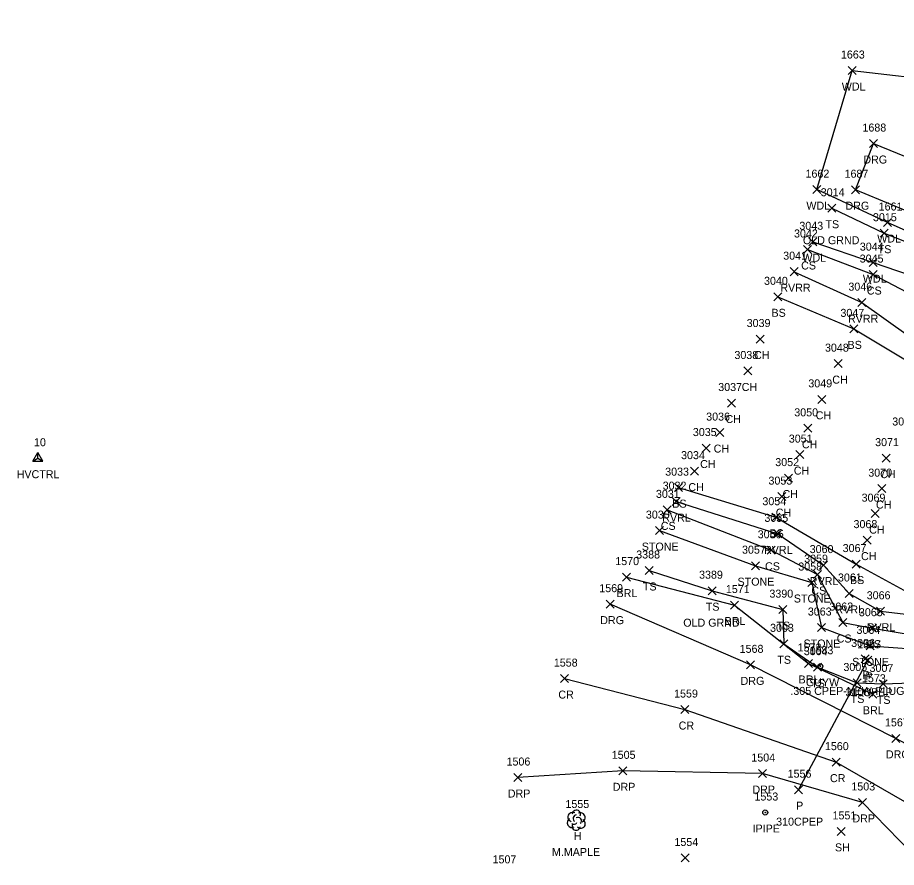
# Model space of a CAD drawing. Extents: x 462930 to 463548, y 29607 to 30453.
# Drawn here: x 463253.6 to 463320.6, y 30111.1 to 30175.8 of the extents above; entities that cross this region are included whole.
import ezdxf

# ---------------------------------------------------------------- set-up
doc = ezdxf.new("R2010")
doc.units = 0
for name, color, linetype in [('C_A', 7, 'Continuous'), ('C_I', 7, 'Continuous'), ('CPSM', 7, 'Continuous'), ('D_A', 7, 'Continuous'), ('D_C', 7, 'Continuous'), ('D_I', 7, 'Continuous'), ('D_TIC', 7, 'Continuous'), ('DCP', 7, 'Continuous'), ('L_A', 7, 'Continuous'), ('L_C', 7, 'Continuous'), ('L_I', 7, 'Continuous'), ('L_TIC', 7, 'Continuous'), ('LABL', 7, 'Continuous'), ('LASF', 7, 'Continuous'), ('LAWA', 7, 'Continuous'), ('LAWE', 7, 'Continuous'), ('LELB', 7, 'Continuous'), ('LTD', 7, 'Continuous'), ('M_A', 7, 'Continuous'), ('M_I', 7, 'Continuous'), ('MPIP', 7, 'Continuous'), ('P_A', 7, 'Continuous'), ('P_I', 7, 'Continuous'), ('P_TIC', 7, 'Continuous'), ('PRC', 7, 'Continuous'), ('R_A', 7, 'Continuous'), ('R_I', 7, 'Continuous'), ('R_TIC', 7, 'Continuous'), ('RDG', 7, 'Continuous'), ('RDP', 7, 'Continuous'), ('U_A', 7, 'Continuous'), ('U_I', 7, 'Continuous'), ('UPGW', 7, 'Continuous')]:
    doc.layers.add(name, color=color, linetype=linetype)

msp = doc.modelspace()

# ---------------------------------------------------------------- linework, layer by layer
at = {"layer": 'CPSM'}
for p, q in [((463254.76, 30142.04), (463255.141, 30142.7)), ((463255.522, 30142.04), (463255.141, 30142.7)), ((463255.141, 30142.26), (463255.141, 30142.7)), ((463254.76, 30142.04), (463255.141, 30142.26)), ((463254.76, 30142.04), (463255.522, 30142.04)), ((463255.141, 30142.26), (463255.141, 30142.26)), ((463255.141, 30142.26), (463255.522, 30142.04))]:
    msp.add_line(p, q, dxfattribs=at)
at = {"layer": 'D_TIC'}
for points in [[(463317.855, 30126.658), (463318.465, 30127.268)], [(463318.465, 30126.658), (463317.855, 30127.268)], [(463318.079, 30126.555), (463318.689, 30127.165)], [(463318.689, 30126.555), (463318.079, 30127.165)], [(463312.796, 30116.692), (463313.406, 30117.302)], [(463313.406, 30116.692), (463312.796, 30117.302)]]:
    msp.add_lwpolyline(points, dxfattribs=at)
at = {"layer": 'DCP'}
msp.add_lwpolyline([(463313.101, 30116.997), (463318.384, 30126.86)], dxfattribs=at)
at = {"layer": 'L_TIC'}
for points in [[(463316.87, 30171.507), (463317.48, 30172.117)], [(463317.48, 30171.507), (463316.87, 30172.117)], [(463314.173, 30162.427), (463314.783, 30163.037)], [(463314.783, 30162.427), (463314.173, 30163.037)], [(463315.327, 30161.009), (463315.937, 30161.619)], [(463315.937, 30161.009), (463315.327, 30161.619)], [(463319.572, 30159.922), (463320.182, 30160.532)], [(463320.182, 30159.922), (463319.572, 30160.532)], [(463319.306, 30159.106), (463319.916, 30159.716)], [(463319.916, 30159.106), (463319.306, 30159.716)], [(463313.464, 30157.866), (463314.074, 30158.475)], [(463314.074, 30157.866), (463313.464, 30158.475)], [(463313.869, 30158.454), (463314.479, 30159.064)], [(463314.479, 30158.454), (463313.869, 30159.064)], [(463318.478, 30156.866), (463319.087, 30157.476)], [(463319.087, 30156.866), (463318.478, 30157.476)], [(463312.466, 30156.175), (463313.076, 30156.785)], [(463313.076, 30156.175), (463312.466, 30156.785)], [(463318.469, 30155.955), (463319.079, 30156.564)], [(463319.079, 30155.955), (463318.469, 30156.564)], [(463311.205, 30154.259), (463311.815, 30154.869)], [(463311.815, 30154.259), (463311.205, 30154.869)], [(463317.623, 30153.814), (463318.232, 30154.424)], [(463318.232, 30153.814), (463317.623, 30154.424)], [(463317, 30151.816), (463317.61, 30152.425)], [(463317.61, 30151.816), (463317, 30152.425)], [(463309.859, 30151.04), (463310.469, 30151.65)], [(463310.469, 30151.04), (463309.859, 30151.65)], [(463315.822, 30149.165), (463316.432, 30149.775)], [(463316.432, 30149.165), (463315.822, 30149.775)], [(463308.921, 30148.605), (463309.531, 30149.215)], [(463309.531, 30148.605), (463308.921, 30149.215)], [(463314.557, 30146.443), (463315.167, 30147.053)], [(463315.167, 30146.443), (463314.557, 30147.053)], [(463307.69, 30146.162), (463308.3, 30146.772)], [(463308.3, 30146.162), (463307.69, 30146.772)], [(463306.788, 30143.909), (463307.397, 30144.519)], [(463307.397, 30143.909), (463306.788, 30144.519)], [(463313.509, 30144.235), (463314.118, 30144.844)], [(463314.118, 30144.235), (463313.509, 30144.844)], [(463305.755, 30142.731), (463306.365, 30143.341)], [(463306.365, 30142.731), (463305.755, 30143.341)], [(463312.894, 30142.232), (463313.504, 30142.842)], [(463313.504, 30142.232), (463312.894, 30142.842)], [(463319.471, 30141.962), (463320.081, 30142.571)], [(463320.081, 30141.962), (463319.471, 30142.571)], [(463304.857, 30140.972), (463305.467, 30141.582)], [(463305.467, 30140.972), (463304.857, 30141.582)], [(463312.033, 30140.44), (463312.643, 30141.049)], [(463312.643, 30140.44), (463312.033, 30141.049)], [(463303.646, 30139.713), (463304.256, 30140.323)], [(463304.256, 30139.713), (463303.646, 30140.323)], [(463319.15, 30139.637), (463319.759, 30140.247)], [(463319.759, 30139.637), (463319.15, 30140.247)], [(463303.456, 30138.646), (463304.065, 30139.256)], [(463304.065, 30138.646), (463303.456, 30139.256)], [(463311.517, 30139.031), (463312.127, 30139.64)], [(463312.127, 30139.031), (463311.517, 30139.64)], [(463302.771, 30138.018), (463303.381, 30138.628)], [(463303.381, 30138.018), (463302.771, 30138.628)], [(463311.053, 30137.459), (463311.663, 30138.068)], [(463311.663, 30137.459), (463311.053, 30138.068)], [(463318.631, 30137.732), (463319.24, 30138.342)], [(463319.24, 30137.732), (463318.631, 30138.342)], [(463302.203, 30136.439), (463302.813, 30137.049)], [(463302.813, 30136.439), (463302.203, 30137.049)], [(463311.208, 30136.192), (463311.818, 30136.802)], [(463311.818, 30136.192), (463311.208, 30136.802)], [(463318.013, 30135.714), (463318.623, 30136.324)], [(463318.623, 30135.714), (463318.013, 30136.324)], [(463310.713, 30134.94), (463311.323, 30135.55)], [(463311.323, 30134.94), (463310.713, 30135.55)], [(463309.502, 30133.766), (463310.111, 30134.375)], [(463310.111, 30133.766), (463309.502, 30134.375)], [(463314.699, 30133.811), (463315.309, 30134.42)], [(463315.309, 30133.811), (463314.699, 30134.42)], [(463317.185, 30133.888), (463317.795, 30134.497)], [(463317.795, 30133.888), (463317.185, 30134.497)], [(463301.416, 30133.399), (463302.026, 30134.009)], [(463302.026, 30133.399), (463301.416, 30134.009)], [(463314.238, 30133.085), (463314.848, 30133.695)], [(463314.848, 30133.085), (463314.238, 30133.695)], [(463299.672, 30132.894), (463300.282, 30133.504)], [(463300.282, 30132.894), (463299.672, 30133.504)], [(463313.792, 30132.482), (463314.402, 30133.091)], [(463314.402, 30132.482), (463313.792, 30133.091)], [(463306.208, 30131.859), (463306.817, 30132.468)], [(463306.817, 30131.859), (463306.208, 30132.468)], [(463316.653, 30131.646), (463317.263, 30132.256)], [(463317.263, 30131.646), (463316.653, 30132.256)], [(463307.901, 30130.765), (463308.511, 30131.375)], [(463308.511, 30130.765), (463307.901, 30131.375)], [(463311.591, 30130.416), (463312.201, 30131.025)], [(463312.201, 30130.416), (463311.591, 30131.025)], [(463319.034, 30130.291), (463319.644, 30130.901)], [(463319.644, 30130.291), (463319.034, 30130.901)], [(463314.53, 30129.051), (463315.14, 30129.66)], [(463315.14, 30129.051), (463314.53, 30129.66)], [(463316.172, 30129.432), (463316.781, 30130.041)], [(463316.781, 30129.432), (463316.172, 30130.041)], [(463318.42, 30129), (463319.03, 30129.61)], [(463319.03, 30129), (463318.42, 30129.61)], [(463311.662, 30127.811), (463312.271, 30128.42)], [(463312.271, 30127.811), (463311.662, 30128.42)], [(463318.238, 30127.653), (463318.848, 30128.263)], [(463318.848, 30127.653), (463318.238, 30128.263)], [(463313.54, 30126.312), (463314.15, 30126.922)], [(463314.15, 30126.312), (463313.54, 30126.922)], [(463314.234, 30126.029), (463314.844, 30126.639)], [(463314.844, 30126.029), (463314.234, 30126.639)], [(463317.252, 30124.825), (463317.861, 30125.434)], [(463317.861, 30124.825), (463317.252, 30125.434)], [(463319.24, 30124.753), (463319.849, 30125.363)], [(463319.849, 30124.753), (463319.24, 30125.363)], [(463318.443, 30123.965), (463319.053, 30124.575)], [(463319.053, 30123.965), (463318.443, 30124.575)], [(463316.028, 30113.512), (463316.638, 30114.122)], [(463316.638, 30113.512), (463316.028, 30114.122)], [(463304.155, 30111.486), (463304.765, 30112.096)], [(463304.765, 30111.486), (463304.155, 30112.096)]]:
    msp.add_lwpolyline(points, dxfattribs=at)
at = {"layer": 'LABL'}
msp.add_lwpolyline([(463299.977, 30133.199), (463308.206, 30131.07), (463313.845, 30126.617), (463318.748, 30124.27)], dxfattribs=at)
at = {"layer": 'LASF'}
msp.add_lwpolyline([(463302.508, 30136.744), (463309.807, 30134.07), (463314.097, 30132.787), (463314.835, 30129.355), (463318.543, 30127.958), (463323.464, 30127.612), (463327.985, 30126.286), (463331.81, 30124.74), (463337.174, 30122.457), (463335.599, 30120.018), (463340.457, 30118.077), (463343.625, 30116.989)], dxfattribs=at)
at = {"layer": 'LAWA'}
for points in [[(463334.191, 30153.632), (463326.241, 30157.391), (463319.877, 30160.227), (463314.478, 30162.732), (463317.175, 30171.812), (463324.684, 30170.939), (463329.084, 30171.282), (463333.083, 30171.461), (463343.25, 30171.173), (463352.596, 30169.581), (463356.899, 30175.447), (463361.663, 30184.45), (463356.272, 30186.994), (463347.611, 30186.575), (463333.194, 30190.781), (463330.167, 30185.817), (463328.348, 30182.689), (463321.007, 30182.589)], [(463314.174, 30158.759), (463318.783, 30157.171), (463323.455, 30155.567), (463328.402, 30153.346), (463330.315, 30151.924), (463334.307, 30149.365)]]:
    msp.add_lwpolyline(points, dxfattribs=at)
at = {"layer": 'LAWE'}
for points in [[(463312.771, 30156.48), (463317.927, 30154.119), (463323.301, 30150.297), (463329.2, 30147.672), (463333.781, 30145.982), (463336.917, 30145.16), (463341.124, 30143.089), (463345.902, 30142.661), (463349.953, 30140.952), (463354.589, 30140.054), (463360.802, 30137.163), (463361.685, 30137.202), (463364.938, 30136.029), (463367.213, 30134.485), (463367.529, 30133.847), (463370.878, 30131.969), (463372.536, 30131.581), (463374.072, 30131.794), (463376.13, 30130.821), (463379.432, 30129.045)], [(463303.761, 30138.951), (463311.513, 30136.497), (463315.004, 30134.116), (463316.958, 30131.951), (463319.339, 30130.596), (463324.938, 30129.932), (463327.547, 30128.313), (463332.975, 30126.47), (463337.641, 30123.674), (463341.966, 30121.958), (463344.49, 30119.626), (463346.795, 30118.444), (463349.584, 30118.528), (463352.681, 30116.677), (463355.961, 30113.875), (463359.993, 30113.221), (463365.135, 30110.482), (463368.778, 30108.638), (463372.593, 30105.432)]]:
    msp.add_lwpolyline(points, dxfattribs=at)
at = {"layer": 'LELB'}
for points in [[(463315.632, 30161.314), (463319.611, 30159.411), (463323.098, 30158.045), (463326.567, 30156.56), (463329.582, 30155.13), (463332.054, 30154.159), (463333.762, 30152.444), (463336.134, 30152.447), (463340.253, 30150.769), (463345.161, 30149.365), (463346.778, 30148.746), (463346.708, 30147.71), (463349.033, 30147.393), (463350.898, 30147.395), (463351.713, 30147.754), (463353.797, 30146.756), (463354.253, 30145.629), (463355.291, 30145.255), (463356.709, 30145.503), (463357.92, 30145.112), (463358.601, 30144.516), (463359.186, 30143.714)], [(463313.769, 30158.17), (463318.774, 30156.259), (463323.868, 30153.596), (463329.249, 30151.11), (463333.551, 30148)], [(463311.51, 30154.564), (463317.305, 30152.12), (463328.108, 30145.648), (463332.48, 30143.532), (463335.24, 30142.565), (463339.678, 30141.183), (463343.544, 30141.846), (463345.752, 30141.37), (463349.534, 30139.719), (463354.026, 30138.661), (463359.587, 30137.022), (463361.306, 30136.712), (463364.334, 30135.56), (463366.649, 30133.733), (463367.281, 30133.213), (463370.369, 30131.577), (463372.89, 30130.394), (463376, 30129.47), (463379.084, 30127.97)], [(463303.951, 30140.018), (463311.358, 30137.763), (463317.49, 30134.193), (463325.042, 30130.081), (463328.062, 30128.844), (463333.248, 30127.486), (463337.89, 30124.253), (463342.916, 30122.365), (463345.021, 30120.043), (463346.984, 30119.167), (463349.819, 30119.192), (463353.514, 30117.826), (463357.518, 30115.65), (463360.726, 30114.785), (463365.845, 30111.76), (463369.152, 30109.504), (463372.544, 30107.449)], [(463303.076, 30138.323), (463311.018, 30135.245), (463314.543, 30133.39), (463316.477, 30129.737), (463318.725, 30129.305), (463323.995, 30128.426), (463327.48, 30127.705), (463332.775, 30125.956), (463337.384, 30123.1), (463341.878, 30121.285), (463344.206, 30119.085), (463346.364, 30117.777), (463348.209, 30116.851), (463350.137, 30117.27)], [(463301.721, 30133.704), (463306.512, 30132.164), (463311.896, 30130.72), (463311.966, 30128.116), (463314.539, 30126.334), (463317.557, 30125.13), (463319.544, 30125.058), (463323.111, 30125.196), (463327.055, 30123.992), (463330.377, 30123.22), (463333.948, 30121.659), (463335.287, 30119.689), (463335.599, 30120.018)]]:
    msp.add_lwpolyline(points, dxfattribs=at)
at = {"layer": 'LTD'}
msp.add_line((463296.155, 30114.687), (463296.155, 30114.687), dxfattribs=at)
msp.add_line((463296.155, 30114.687), (463296.155, 30114.687), dxfattribs=at)
msp.add_arc((463296.169, 30115.124), 0.319, 335.52715, 180.95627, dxfattribs=at)
for centre, major_axis, ratio, start_param, end_param in [((463295.914, 30114.89), (0.369, -0.156), 0.895232, 1.570796, 4.712389), ((463296.091, 30114.827), (-0.063, -0.241), 0.645439, 3.141593, 6.283185), ((463296.307, 30114.636), (-0.152, 0.203), 0.989748, 3.141593, 6.283185), ((463296.472, 30114.865), (-0.348, -0.147), 0.949671, 1.570796, 4.712389), ((463295.825, 30114.471), (0.178, -0.317), 0.959034, 3.141593, 6.283185), ((463296.155, 30114.23), (0.081, 0.323), 0.942809, 1.570796, 4.712389), ((463296.015, 30114.458), (-0.19, -0.025), 0.423636, 0, 3.141593), ((463296.46, 30114.433), (-0.332, 0.241), 0.841452, 1.570796, 4.712389)]:
    msp.add_ellipse(centre, major_axis=major_axis, ratio=ratio, start_param=start_param, end_param=end_param, dxfattribs=at)
at = {"layer": 'MPIP'}
for radius in [0.191, 0.0254]:
    msp.add_circle((463310.559, 30115.257), radius, dxfattribs=at)
at = {"layer": 'P_TIC'}
for points in [[(463294.966, 30125.159), (463295.576, 30125.769)], [(463295.576, 30125.159), (463294.966, 30125.769)], [(463304.132, 30122.799), (463304.742, 30123.409)], [(463304.742, 30122.799), (463304.132, 30123.409)], [(463315.662, 30118.791), (463316.272, 30119.401)], [(463316.272, 30118.791), (463315.662, 30119.401)]]:
    msp.add_lwpolyline(points, dxfattribs=at)
at = {"layer": 'PRC'}
msp.add_lwpolyline([(463295.271, 30125.464), (463304.437, 30123.104), (463315.967, 30119.096), (463324.689, 30114.057), (463329.655, 30111.118)], dxfattribs=at)
at = {"layer": 'R_TIC'}
for points in [[(463318.495, 30165.941), (463319.105, 30166.551)], [(463319.105, 30165.941), (463318.495, 30166.551)], [(463317.133, 30162.423), (463317.743, 30163.033)], [(463317.743, 30162.423), (463317.133, 30163.033)], [(463298.446, 30130.832), (463299.056, 30131.442)], [(463299.056, 30130.832), (463298.446, 30131.442)], [(463309.139, 30126.207), (463309.749, 30126.817)], [(463309.749, 30126.207), (463309.139, 30126.817)], [(463320.214, 30120.602), (463320.824, 30121.212)], [(463320.824, 30120.602), (463320.214, 30121.212)], [(463299.403, 30118.129), (463300.013, 30118.739)], [(463300.013, 30118.129), (463299.403, 30118.739)], [(463310.04, 30117.922), (463310.65, 30118.532)], [(463310.65, 30117.922), (463310.04, 30118.532)], [(463291.404, 30117.619), (463292.014, 30118.229)], [(463292.014, 30117.619), (463291.404, 30118.229)], [(463317.66, 30115.718), (463318.27, 30116.328)], [(463318.27, 30115.718), (463317.66, 30116.328)]]:
    msp.add_lwpolyline(points, dxfattribs=at)
at = {"layer": 'RDG'}
for points in [[(463347.931, 30153.415), (463337.62, 30154.896), (463328.703, 30158.04), (463317.438, 30162.728), (463318.8, 30166.246), (463327.27, 30162.794), (463340.451, 30158.117), (463344.729, 30166.901), (463353.138, 30164.992), (463357.576, 30167.469)], [(463329.782, 30115.965), (463320.519, 30120.907), (463309.444, 30126.512), (463298.751, 30131.137)]]:
    msp.add_lwpolyline(points, dxfattribs=at)
at = {"layer": 'RDP'}
msp.add_lwpolyline([(463319.513, 30094.018), (463322.216, 30104.589), (463322.678, 30111.184), (463317.965, 30116.023), (463310.345, 30118.227), (463299.708, 30118.434), (463291.709, 30117.924)], dxfattribs=at)
at = {"layer": 'UPGW'}
for radius in [0.191, 0.0254]:
    msp.add_circle((463314.757, 30126.406), radius, dxfattribs=at)

# ---------------------------------------------------------------- texts
at = {"layer": 'C_A'}
msp.add_text('HVCTRL', height=0.6096, dxfattribs=at).set_placement((463253.523, 30140.736))
at = {"layer": 'C_I'}
msp.add_text('10', height=0.6096, dxfattribs=at).set_placement((463254.841, 30143.174))
at = {"layer": 'D_A'}
for p in [(463317.97, 30125.439), (463318.194, 30125.336), (463312.911, 30115.473)]:
    msp.add_text('P', height=0.61, dxfattribs=at).set_placement(p)
at = {"layer": 'D_C'}
for s, p in [('.305 CPEP-NEW-PLUGGED', (463312.474, 30124.22)), ('310CPEP', (463316.673, 30124.117)), ('310CPEP', (463311.39, 30114.254))]:
    msp.add_text(s, height=0.6096, dxfattribs=at).set_placement(p)
at = {"layer": 'D_I'}
for s, p in [('3006', (463317.102, 30127.877)), ('1557', (463317.563, 30127.774)), ('1556', (463312.263, 30117.911))]:
    msp.add_text(s, height=0.6096, dxfattribs=at).set_placement(p)
at = {"layer": 'L_A'}
for s, height, p in [('WDL', 0.6096, (463316.388, 30170.288)), ('WDL', 0.6096, (463313.691, 30161.208)), ('TS', 0.6096, (463315.147, 30159.79)), ('WDL', 0.6096, (463319.09, 30158.703)), ('TS', 0.6096, (463319.126, 30157.887)), ('WDL', 0.6096, (463313.387, 30157.235)), ('CS', 0.6096, (463313.294, 30156.646)), ('WDL', 0.6096, (463317.995, 30155.647)), ('RVRR', 0.6096, (463311.708, 30154.956)), ('CS', 0.6096, (463318.299, 30154.735)), ('BS', 0.6096, (463311.035, 30153.04)), ('RVRR', 0.6096, (463316.864, 30152.595)), ('BS', 0.6096, (463316.83, 30150.596)), ('CH', 0.6096, (463309.703, 30149.821)), ('CH', 0.6096, (463315.666, 30147.946)), ('CH', 0.6096, (463308.765, 30147.386)), ('CH', 0.6096, (463314.401, 30145.224)), ('CH', 0.6096, (463307.534, 30144.943)), ('CH', 0.6096, (463306.632, 30142.69)), ('CH', 0.6096, (463313.353, 30143.015)), ('CH', 0.6096, (463305.599, 30141.512)), ('CH', 0.6096, (463312.738, 30141.013)), ('CH', 0.6096, (463319.315, 30140.743)), ('CH', 0.6096, (463304.701, 30139.753)), ('CH', 0.6096, (463311.877, 30139.221)), ('BS', 0.6096, (463303.476, 30138.494)), ('CH', 0.6096, (463318.994, 30138.418)), ('CH', 0.6096, (463311.361, 30137.811)), ('RVRL', 0.6096, (463302.714, 30137.427)), ('CS', 0.6096, (463302.601, 30136.799)), ('CH', 0.6096, (463318.475, 30136.513)), ('BS', 0.6096, (463310.883, 30136.239)), ('STONE', 0.6096, (463301.15, 30135.22)), ('RVRL', 0.6096, (463310.467, 30134.973)), ('CH', 0.6096, (463317.857, 30134.495)), ('CS', 0.6096, (463310.543, 30133.721)), ('STONE', 0.6096, (463308.448, 30132.546)), ('RVRL', 0.6096, (463313.957, 30132.592)), ('BS', 0.6096, (463317.015, 30132.669)), ('TS', 0.6096, (463301.236, 30132.18)), ('CS', 0.6096, (463314.068, 30131.866)), ('BRL', 0.6096, (463299.228, 30131.675)), ('STONE', 0.6096, (463312.739, 30131.263)), ('TS', 0.6096, (463306.028, 30130.64)), ('RVRL', 0.6096, (463315.912, 30130.427)), ('BRL', 0.6096, (463307.457, 30129.546)), ('TS', 0.6096, (463311.411, 30129.196)), ('RVRL', 0.6096, (463318.293, 30129.072)), ('STONE', 0.6096, (463313.477, 30127.831)), ('CS', 0.6096, (463316.001, 30128.213)), ('CS', 0.6096, (463318.25, 30127.781)), ('TS', 0.6096, (463311.482, 30126.592)), ('STONE', 0.6096, (463317.185, 30126.434)), ('BRL', 0.6096, (463313.096, 30125.093)), ('TS', 0.6096, (463314.054, 30124.81)), ('TS', 0.6096, (463317.072, 30123.606)), ('TS', 0.6096, (463319.06, 30123.534)), ('BRL', 0.6096, (463317.999, 30122.746)), ('H', 0.61, (463295.982, 30113.163)), ('SH', 0.6096, (463315.872, 30112.293))]:
    msp.add_text(s, height=height, dxfattribs=at).set_placement(p)
at = {"layer": 'L_C'}
for s, p in [('OLD GRND', (463313.431, 30158.571)), ('OLD GRND', (463304.312, 30129.42)), ('M.MAPLE', (463294.307, 30111.944))]:
    msp.add_text(s, height=0.6096, dxfattribs=at).set_placement(p)
at = {"layer": 'L_I'}
for s, p in [('1663', (463316.325, 30172.726)), ('1662', (463313.628, 30163.646)), ('3014', (463314.788, 30162.228)), ('1661', (463319.2, 30161.141)), ('3015', (463318.766, 30160.326)), ('3043', (463313.157, 30159.674)), ('3042', (463312.751, 30159.085)), ('3044', (463317.765, 30158.085)), ('3041', (463311.926, 30157.395)), ('3045', (463317.757, 30157.174)), ('3040', (463310.466, 30155.478)), ('3046', (463316.893, 30155.034)), ('3047', (463316.288, 30153.035)), ('3039', (463309.144, 30152.259)), ('3038', (463308.209, 30149.824)), ('3048', (463315.11, 30150.384)), ('3037', (463306.977, 30147.382)), ('3049', (463313.842, 30147.662)), ('3036', (463306.058, 30145.128)), ('3050', (463312.77, 30145.454)), ('3072', (463320.235, 30144.754)), ('3035', (463305.042, 30143.95)), ('3051', (463312.354, 30143.451)), ('3071', (463318.931, 30143.181)), ('3034', (463304.144, 30142.191)), ('3052', (463311.321, 30141.659)), ('3033', (463302.933, 30140.932)), ('3070', (463318.41, 30140.857)), ('3032', (463302.743, 30139.865)), ('3053', (463310.804, 30140.25)), ('3031', (463302.231, 30139.238)), ('3054', (463310.341, 30138.678)), ('3069', (463317.901, 30138.951)), ('3030', (463301.464, 30137.659)), ('3055', (463310.496, 30137.411)), ('3068', (463317.286, 30136.933)), ('3056', (463309.984, 30136.159)), ('3067', (463316.458, 30135.107)), ('3388', (463300.727, 30134.618)), ('3057', (463308.789, 30134.985)), ('3060', (463313.945, 30135.03)), ('1570', (463299.13, 30134.113)), ('3059', (463313.523, 30134.304)), ('3389', (463305.516, 30133.078)), ('3058', (463313.079, 30133.701)), ('3061', (463316.099, 30132.865)), ('1571', (463307.558, 30131.984)), ('3390', (463310.876, 30131.635)), ('3066', (463318.29, 30131.511)), ('3062', (463315.445, 30130.651)), ('3063', (463313.803, 30130.27)), ('3065', (463317.693, 30130.219)), ('3003', (463310.925, 30129.03)), ('3064', (463317.511, 30128.872)), ('1572', (463313.024, 30127.531)), ('3004', (463313.498, 30127.249)), ('3005', (463316.515, 30126.044)), ('3007', (463318.503, 30125.972)), ('1573', (463317.927, 30125.184)), ('1555', (463295.334, 30115.601)), ('1551', (463315.685, 30114.731)), ('1554', (463303.639, 30112.705)), ('1507', (463289.782, 30111.382))]:
    msp.add_text(s, height=0.6096, dxfattribs=at).set_placement(p)
at = {"layer": 'M_A'}
msp.add_text('IPIPE', height=0.6096, dxfattribs=at).set_placement((463309.594, 30113.733))
at = {"layer": 'M_I'}
msp.add_text('1553', height=0.6096, dxfattribs=at).set_placement((463309.738, 30116.171))
at = {"layer": 'P_A'}
for p in [(463294.793, 30123.94), (463303.959, 30121.58), (463315.489, 30117.572)]:
    msp.add_text('CR', height=0.6096, dxfattribs=at).set_placement(p)
at = {"layer": 'P_I'}
for s, p in [('1558', (463294.45, 30126.378)), ('1559', (463303.614, 30124.018)), ('1560', (463315.105, 30120.01))]:
    msp.add_text(s, height=0.6096, dxfattribs=at).set_placement(p)
at = {"layer": 'R_A'}
for s, p in [('DRG', (463318.034, 30164.722)), ('DRG', (463316.672, 30161.204)), ('DRG', (463297.985, 30129.613)), ('DRG', (463308.678, 30124.988)), ('DRG', (463319.753, 30119.383)), ('DRP', (463290.943, 30116.4)), ('DRP', (463298.942, 30116.91)), ('DRP', (463309.579, 30116.703)), ('DRP', (463317.199, 30114.499))]:
    msp.add_text(s, height=0.6096, dxfattribs=at).set_placement(p)
at = {"layer": 'R_I'}
for s, p in [('1688', (463317.965, 30167.16)), ('1687', (463316.603, 30163.642)), ('1569', (463297.913, 30132.051)), ('1568', (463308.609, 30127.426)), ('1567', (463319.684, 30121.821)), ('1505', (463298.863, 30119.348)), ('1504', (463309.5, 30119.141)), ('1506', (463290.847, 30118.838)), ('1503', (463317.12, 30116.937))]:
    msp.add_text(s, height=0.6096, dxfattribs=at).set_placement(p)
at = {"layer": 'U_A'}
msp.add_text('GUYW', height=0.6096, dxfattribs=at).set_placement((463313.658, 30124.882))
at = {"layer": 'U_I'}
msp.add_text('1583', height=0.6096, dxfattribs=at).set_placement((463313.936, 30127.32))

doc.saveas('drawing.dxf')
